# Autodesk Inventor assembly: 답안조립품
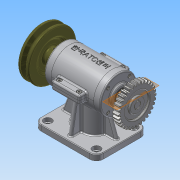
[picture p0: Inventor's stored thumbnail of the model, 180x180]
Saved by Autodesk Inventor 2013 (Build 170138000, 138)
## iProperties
Created: 2015-09
Part Number: 답안조립품
Document SubType Name: Assembly
Designer: Administrator
Mass: 2251.17 g
Surface Area: 1633.51 cm^2
Volume: 528.515 cm^3
Density: 4.25943 g/cm^3
Author: Administrator
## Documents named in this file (17)
- C:\Users\Administrator\Desktop\350908V1029\답안조립품.iam
- C:\Users\Administrator\Desktop\350908V1029\본체.ipt
- C:\Users\Administrator\Desktop\350908V1029\M3x0.5x8.ipt
- C:\Users\Administrator\Desktop\350908V1029\M4x0.5x14.ipt
- C:\Users\Administrator\Desktop\350908V1029\V-벨트풀리.ipt
- C:\Users\Administrator\Desktop\350908V1029\가변스프링.ipt
- C:\Users\Administrator\Desktop\350908V1029\뒤커버.ipt
- C:\Users\Administrator\Desktop\350908V1029\멈춤나사.ipt
- C:\Users\Administrator\Desktop\350908V1029\베어링 6201.ipt
- C:\Users\Administrator\Desktop\350908V1029\베어링 6202.ipt
- C:\Users\Administrator\Desktop\350908V1029\본체 커버.ipt
- C:\Users\Administrator\Desktop\350908V1029\스퍼기어.ipt
- C:\Users\Administrator\Desktop\350908V1029\슬라이드.ipt
- C:\Users\Administrator\Desktop\350908V1029\앞커버.ipt
- C:\Users\Administrator\Desktop\350908V1029\오일실.ipt
- C:\Users\Administrator\Desktop\350908V1029\키4x4.ipt
- C:\Users\Administrator\Desktop\350908V1029\편심축.ipt
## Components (14 placed, 4 different names)
1. M4x0.5x14:1
2. V-벨트풀리:1 — 플러쉬:2, 각도:1
3. 가변스프링:1
4. M4x0.5x14:2
5. M4x0.5x14:3
6. M4x0.5x14:4
7. M3x0.5x8:1
8. M3x0.5x8:3
9. M3x0.5x8:4
10. M3x0.5x8:5
11. M3x0.5x8:2
12. M3x0.5x8:6
13. M3x0.5x8:7
14. M3x0.5x8:8
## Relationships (2: Flush 1, Angle 1)
- 플러쉬:2 [Flush]: V-벨트풀리:1
- 각도:1 [Angle]: V-벨트풀리:1
